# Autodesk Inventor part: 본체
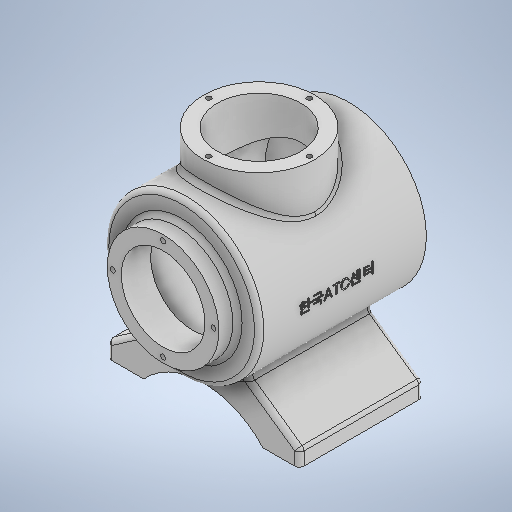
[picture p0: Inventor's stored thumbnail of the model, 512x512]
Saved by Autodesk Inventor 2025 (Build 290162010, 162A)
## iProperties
Created: 2024-07
Part Number: 본체
Material: 일반
Document SubType Name: Modeling
Designer: 학생
Density: 1 g/cm^3
Appearance: 기본값
Author: 학생
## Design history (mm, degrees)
sketch "스케치1"
  geometry: L1 (-62, 0)-(62, 0); L2 (-62, 0)-(-62, 10); L3 (62, 0)-(62, 10); L4 (-62, 10)-(-6.469, 48.883); L5 (62, 10)-(6.469, 48.883); L6 (-6.469, 48.883)-(6.469, 48.883); L7 (-102.897, 17)-(111.482, 17); C1 r 52 at (0, -35); 2 further points
  constraints: 14 end point, 3 horizontal, 2 vertical, 1 centre point, 1 coincident, 1 midpoint, 1 tangent
  dimensions: "d0" = 124 distance of L1.start L1.end; "d1" = 10 distance of L1.start L2.end; "d3" = 10 distance of L1.end L3.end; "d4" = 55 deg angle of L4 L2; "d5" = 55 deg angle of L5 L3; "d21" = 17 distance between parallel lines of L1 L7; "d23" = 104 diameter of C1
extrude "돌출1" new body sketch "스케치1" stored distance "d6" = 80; taper "d7" = 0 deg
sketch "스케치2"
  geometry: C1 r 50 at (0, 77); 1 further point
  constraints: 1 centre point
  dimensions: "d8" = 100 diameter of C1; "d9" = 77 distance of point (0, 0) C1.centre
extrude "돌출2" join sketch "스케치2" stored distance "d10" = 108; taper "d11" = 0 deg
sketch "스케치3"
  geometry: C1 r 36 at (0, 0); 1 further point
  constraints: 1 centre point
  dimensions: "d12" = 72 diameter of C1
extrude "돌출3" join sketch "스케치3" distance "d13" = 12; taper "d14" = 0 deg
node "작업 평면1"
extrude "돌출5" cut sketch "스케치1" stored distance "d24" = 124; taper "d25" = 0 deg
node "작업 평면2"
node "작업 평면3"
sketch "스케치6"
  geometry: L1 (36, 66)-(-36, 66) reference; C1 r 36 at (0, 4); 1 further point
  constraints: 1 centre point
  dimensions: "d32" = 72 diameter of C1; "d33" = 62 distance from line of C1.centre L1
extrude "돌출7" join sketch "스케치6" stored distance "d34" = 10; taper "d35" = 0 deg
sketch "스케치7"
  geometry: C1 r 27 at (0, 0); 1 further point
  constraints: 1 centre point
  dimensions: "d36" = 54 diameter of C1
sketch "스케치8"
  geometry: C1 r 27 at (0, 0); 1 further point
  constraints: 1 centre point
  dimensions: "d37" = 54 diameter of C1
extrude "돌출8" cut sketch "스케치7" distance "d38" = 19; taper "d39" = 0 deg
sketch "스케치9"
  geometry: C1 r 43 at (0, 0); 1 further point
  constraints: 1 centre point
  dimensions: "d40" = 86 diameter of C1
extrude "돌출9" cut sketch "스케치9" distance "d41" = 90; taper "d42" = 0 deg
extrude "돌출10" cut sketch "스케치8" distance "d43" = 40; taper "d44" = 0 deg
fillet "모깎기1" dims "d45" = 3
fillet "모깎기2" dims "d46" = 3
sketch "스케치10" dims "d47" = 65
  geometry: 3 further points
  constraints: 2 vertical alignment, 2 other
hole "구멍1" sketch "스케치10" at (0, 32.5) diameter "d48" = 3.242; stored, may be unused: countersink angle "d52" = 90 deg, drill point angle "d54" = 118 deg; dims "d49" = 8, "d50" = 4, "d51" = 2, "d53" = 10
sketch "스케치11" dims "d58" = 65
  geometry: 3 further points
  constraints: 2 horizontal alignment, 2 other
hole "구멍2" sketch "스케치11" at (-32.5, 0) diameter "d59" = 3.242; stored, may be unused: countersink angle "d63" = 90 deg, drill point angle "d65" = 118 deg; dims "d60" = 8, "d61" = 4, "d62" = 2, "d64" = 10
node "작업 평면4"
sketch "스케치12"
  geometry: L1 (113, 66)-(41, 66) reference; 3 further points
  constraints: 1 midpoint, 1 vertical alignment, 1 other
  dimensions: "d72" = 62 distance from line of point (77, 4) L1
feature "엠보싱1" sketch "스케치12" dims "d0" = 124, "d1" = 10, "d3" = 10, "d4" = 55 deg, "d5" = 55 deg, "d21" = 17, "d23" = 104, "d70" = 0.5, "d71" = 0
node "솔리드1"
pattern_circular "원형 패턴1" dims angle "d56" = 360 deg
pattern_circular "원형 패턴2" dims angle "d67" = 360 deg
feature "A9D066F2-1C7D-4E18-AEED-F7BC21143FA4" dims "d48" = 3.242, "d49" = 8, "d50" = 4, "d51" = 2, "d52" = 90 deg, "d53" = 10, "d54" = 118 deg
other parameters: "d15" = 142, "d26" = 174, "d31" = 142, "d69" = 105
